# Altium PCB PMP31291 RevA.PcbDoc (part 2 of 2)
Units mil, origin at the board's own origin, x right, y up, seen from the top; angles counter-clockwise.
Board outline 2106.3 x 1624.03 mil, 4 copper layers (Top Layer, Layer 2, Layer 3, Bottom Layer), stack 73.2 mil thick; 65 components, 32 nets, 159 pads, 133 vias.
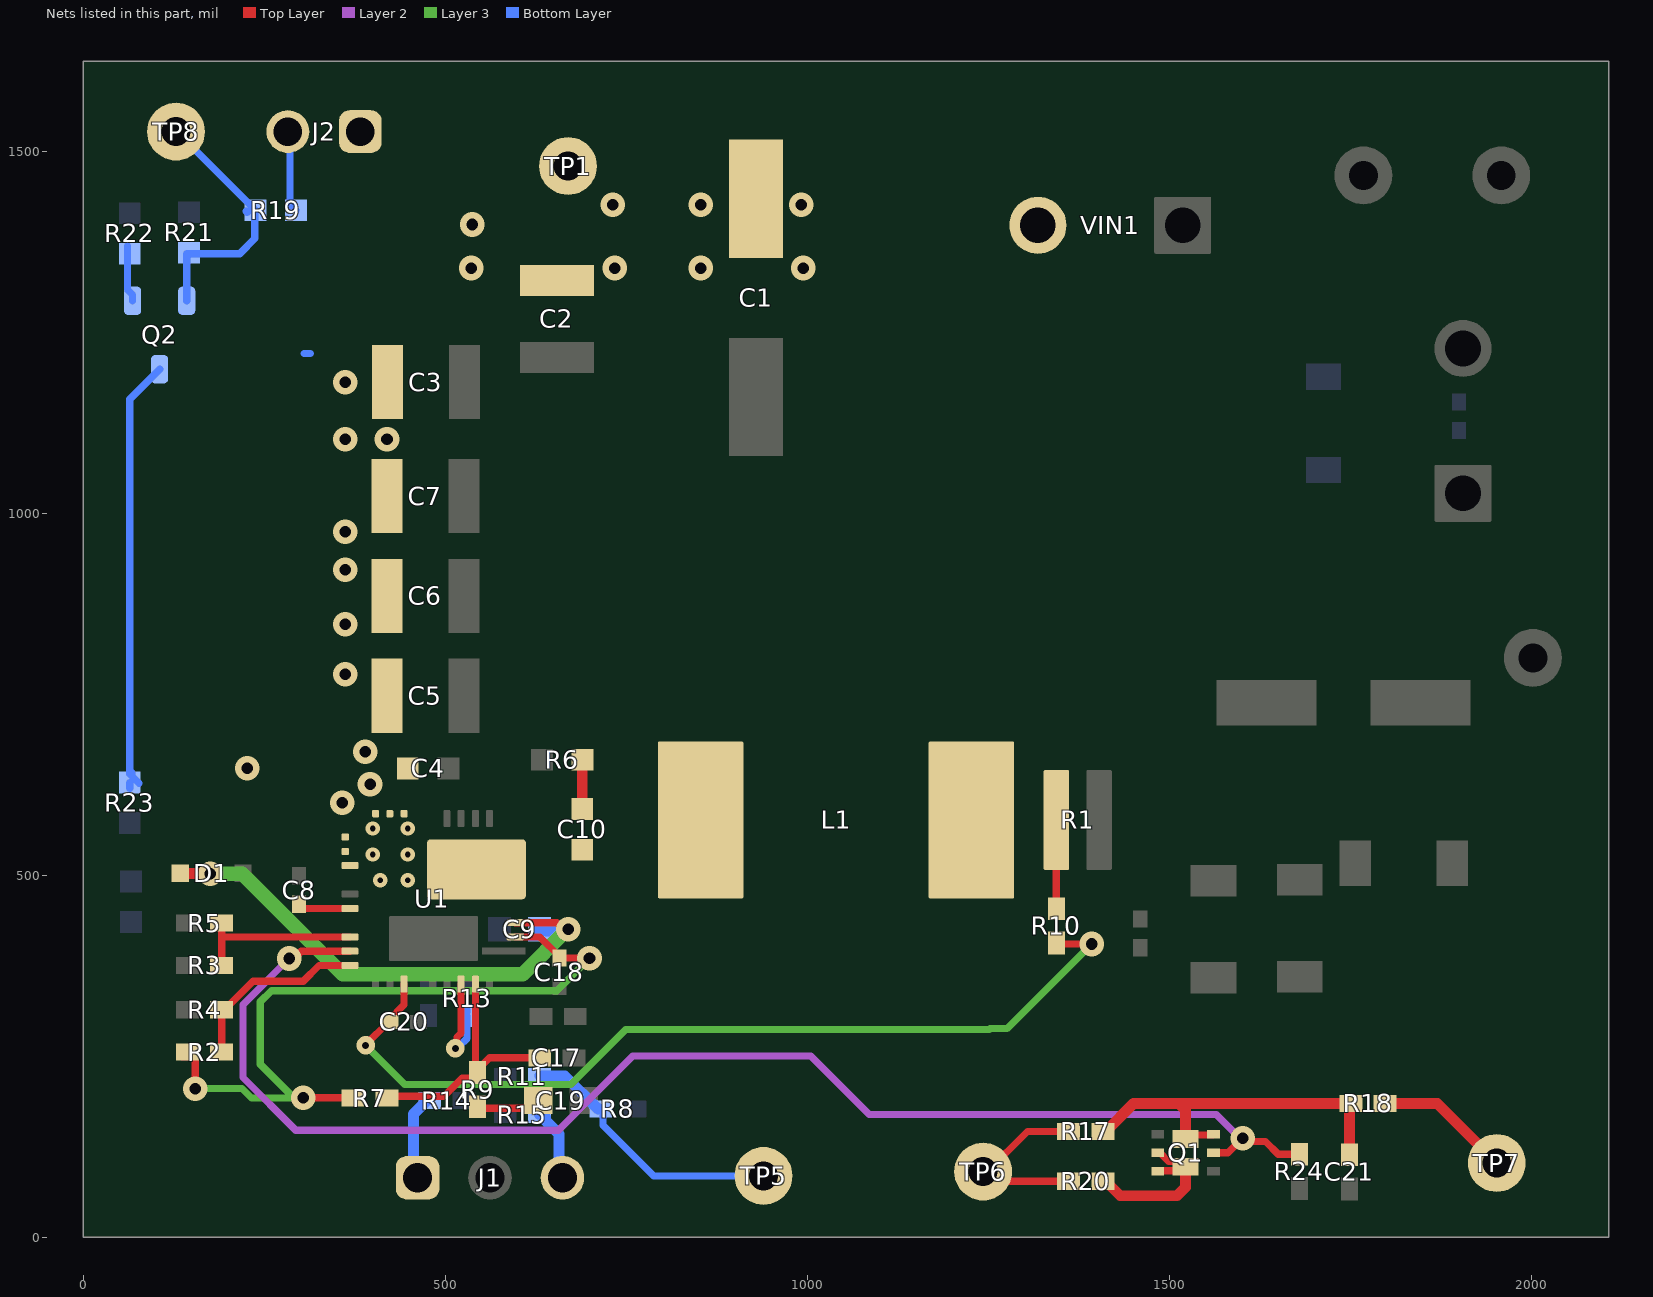
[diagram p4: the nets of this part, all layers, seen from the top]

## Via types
v1: diameter 34, hole 16, Top Layer to Bottom Layer, tented both sides, 117 vias
v2: diameter 19.68, hole 7.87, Top Layer to Bottom Layer, 12 vias
v3: diameter 25.75, hole 10, Top Layer to Bottom Layer, tented both sides, 4 vias

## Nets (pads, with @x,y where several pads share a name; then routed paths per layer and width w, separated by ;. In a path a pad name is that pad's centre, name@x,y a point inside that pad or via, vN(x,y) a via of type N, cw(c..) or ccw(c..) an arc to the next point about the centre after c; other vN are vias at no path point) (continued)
NetC10_2: C10.2 R6.1 | length 63.1
  Top Layer w10: R6.1@688.98,659.03 R6.1@689.39,659.45
  Top Layer w15: C10.2@688.98,596.51 R6.1@688.98,659.03
NetC17_1: C17.1 R7.1 R9.2 U1.15 | length 364.1
  Top Layer w10: R7.1@412.23,194.78 498.03,194.78 523.34,220.09 538.66,220.09 R9.2@544.29,225.72 ; U1.15@541.34,350 541.34,343.27 541.48,343.13 R9.2@541.48,227.56 ; R9.2@544.29,227.56 544.29,231.49 560.72,247.92 C17.1@630.28,247.92
NetC19_1: C19.1 R9.1 | length 81.3
  Top Layer w10: R9.1@544.29,178.47 C19.1@625.59,178.47
NetC20_2: C20.2 R10.2 U1.11 | length 1261.7
  Top Layer w10: v3(389.75,265.16) 389.75,266.01 421.26,297.52 C20.2@423.23,297.52 ; C20.2@421.22,299.53 442.91,321.22 U1.11@442.91,350 ; R10.2@1343.64,406.7 1345.17,405.16 v1(1392.46,405.16)
  Layer 3 w10: v3(389.75,265.16) 443.69,211.22 672.92,211.22 748.94,287.24 1251.05,287.24 1252.09,288.29 1275.59,288.29 v1(1392.46,405.16)
NetC21_1: C21.1 Q1.3 Q1.8 R17.1 R18.2 | length 523.8
  Top Layer w10: R17.1@1407.86,146.38 R17.1@1411.8,146.38 ; Q1.8@1522.04,136.06 1527.51,141.53 1559.52,141.53 Q1.3@1560.42,142.44 ; R18.2@1748.41,182.95 R18.2@1750.38,184.92
  Top Layer w15: R17.1@1411.8,146.38 1450.34,184.92 1513.02,184.92 ; Q1.8@1522.04,136.06 1522.04,175.9 1513.02,184.92 ; C21.1@1748.41,114.04 R18.2@1748.41,182.95 ; R18.2@1750.38,184.92 1513.02,184.92
NetJ1_1: J1.1 R14.1 | length 124.1
  Bottom Layer w10: R14.1@474.41,188.93 R14.1@478.35,188.93
  Bottom Layer w15: J1.1@455.71,76.52 455.71,170.23 R14.1@474.41,188.93
NetJ1_3: J1.3 R15.1 | length 105.6
  Bottom Layer w15: R15.1@629.87,169.7 633.81,169.7 638.12,165.39 638.12,161.46 656.65,142.92 J1.3@656.65,77.47
NetJ2_2: J2.2 R19.2 | length 123.7
  Bottom Layer w10: J2.2@282.45,1527.06 285.31,1524.2 285.31,1426.86 R19.2@293.75,1418.42 ; J2.2@289.76,1519.74 J2.2@297.08,1527.06
NetL1_2: L1.2 R1.1 R10.1 | length 122.5
  Top Layer w10: R10.1@1343.64,453.94 R1.1@1343.64,576.41
NetQ1_5: Q1.5 Q1.6 Q1.7 R20.1 | length 243.1
  Top Layer w10: R20.1@1407.86,77.48 R20.1@1411.8,77.48 ; Q1.6@1483.65,91.26 1484.56,92.16 1516.56,92.16 Q1.7@1522.04,97.64 1514.73,104.94 1498.51,104.94 1486.6,116.85 Q1.5@1483.65,116.85
  Top Layer w15: R20.1@1411.8,77.48 1431.78,57.5 1510.35,57.5 1522.04,69.19 1522.04,92.16 Q1.7@1522.04,97.64
NetQ2_1: Q2.1 R22.2 | length 79.2
  Bottom Layer w10: R22.2@60.78,1369.64 60.78,1308.91 67.94,1301.75 Q2.1@67.94,1293.39
NetQ2_2: Q2.2 R19.1 R21.2 TP8.1 | length 371.2
  Bottom Layer w10: TP8.1@127.95,1527.06 129.11,1527.06 R19.1@237.75,1418.42 236.77,1417.45 236.77,1379.24 215.97,1358.44 143.73,1358.44 R21.2@145.99,1356.18 ; Q2.2@142.74,1293.39 R21.2@142.74,1358.44 ; R19.1@224.7,1416.91 226.43,1415.17 R19.1@229.55,1418.29
NetQ2_3: Q2.3 R23.2 | length 609.2
  Bottom Layer w10: R23.2@63.98,619.73 R23.2@63.98,628.17 ; R23.2@65.73,642.87 66.96,641.64 R23.2@66.96,637.01 ; R23.2@76.96,627.01 R23.2@66.96,637.01 ; Q2.3@105.34,1198.9 63.98,1157.53 63.98,639.99 R23.2@66.96,637.01
NetR2_1: R2.1 R4.2 U1.8 | length 261
  Top Layer w10: R2.1@190.94,255.91 R4.2@190.94,314.34 194.88,314.34 234.25,353.71 303.49,353.71 325.37,375.59 U1.8@368.11,375.59
NetR3_1: R3.1 R5.2 U1.6 | length 234
  Top Layer w10: R3.1@190.94,375.59 190.94,413.39 R5.2@190.94,434.02 ; 192.52,414.96 258.75,414.96 U1.6@368.11,414.96
NetR8_1: R8.1 R11.2 TP5.1 | length 377.5
  Bottom Layer w10: R11.2@629.87,222.35 R11.2@630.83,223.31 ; R8.1@717.42,177.49 717.42,154.74 787.22,84.95 TP5.1@939.23,84.95
  Bottom Layer w15: R11.2@630.83,223.31 664.81,223.31 710.63,177.49 R8.1@714.57,177.49
NetR17_2: R17.2 R20.2 TP6.1 | length 272.7
  Top Layer w10: TP6.1@1234.93,77.48 R20.2@1360.62,77.48 ; TP6.1@1236.6,90.84 1248.29,90.84 1303.83,146.38 R17.2@1360.62,146.38
NetR18_1: R18.1 TP7.1 | length 188.2
  Top Layer w15: R18.1@1797.63,184.92 1869.6,184.92 TP7.1@1951.79,102.72
PG: Q1.2 R24.2 U1.7 | length 1924.3
  Top Layer w10: v1(284.1,385.09) 290.59,385.09 300.78,395.28 U1.7@368.11,395.28 ; Q1.2@1560.42,116.85 1580.63,116.85 v1(1600.78,137) 1605.37,132.4 1632.47,132.4 1649.99,114.88 R24.2@1679.36,114.88 R24.2@1679.36,118.82
  Layer 2 w10: v1(284.1,385.09) 220.37,321.36 220.37,220.84 293.11,148.1 656.27,148.1 758.68,250.51 1004.47,250.51 1085.27,169.7 1564.38,169.7 1597.09,137 v1(1600.78,137)
  Bottom Layer w10: v1@280.54,381.53 v1(284.1,385.09)
RT: R13.2 U1.14 | length 145.2
  Top Layer w10: v3@514.03,261.91 515.88,263.77 515.88,276.58 521.65,282.34 U1.14@521.65,350
  Bottom Layer w10: v3@518.7,260.96 518.7,263.59 529.94,274.83 R13.2@529.94,306.32 ; R13.2@529.94,310.78 R13.2@529.94,314.72
  other v3: 513.76,260.96
SW: C10.1 L1.1 U1. U1.20 U1.21 U1.22 | length 0.1
  Top Layer w10: U1.22@602.52,533.07 U1.@602.6,532.99
SW1: C8.2 U1.5 | length 73.9
  Top Layer w10: C8.2@297.83,460.79 297.83,459.17 302.67,454.33 U1.5@368.11,454.33
VCC: C9.1 D1.2 U1.19 | length 738.3
  Top Layer w10: D1.2@132.99,502.01 D1.2@133.86,502.87 ; U1.19@596.46,434.65 653.9,434.65 662.96,425.59 v1(669.45,425.59)
  Top Layer w15: D1.2@132.99,502.01 134.61,503.62 135.79,502.44 174.82,502.44 v1(175.26,502.01)
  Layer 3 w20: v1(175.26,502.01) 219.58,502.01 296.22,425.36 357.96,363.62 606.51,363.62 668.48,425.59 v1(669.45,425.59)
  Bottom Layer w20: C9.1@629.87,425.59 v1(669.45,425.59)
VDDA: C18.2 R2.2 R7.2 U1.18 | length 1033.9
  Top Layer w10: R2.2@136.89,249.09 R2.2@143.7,249.09 ; R2.2@143.7,255.91 147.64,255.91 154.45,249.09 v1(154.45,205.5) ; v1(303.49,192.98) 303.74,192.73 371.64,192.73 R7.2@371.89,192.48 ; U1.18@596.46,414.96 630.31,414.96 657.51,387.77 C18.2@657.51,385.8 657.59,385.72 698.9,385.72 v1(698.98,385.63)
  Layer 3 w10: v1(154.45,205.5) 219.2,205.5 232.22,192.48 v1@290.48,192.48 ; v1(303.49,192.98) 290.48,192.98 244.37,239.08 244.37,325.45 259.67,340.75 654.09,340.75 v1(698.98,385.63)
VIN: C1.1 C2.1 C3.1 C4.1 C5.1 C6.1 C7.1 J2.1 TP1.1 U1.1 U1.2 U1.3 U1.27 U1.28 U1.29 VIN1.2 | length 8.5
  Bottom Layer w10: 305.07,1220.47 313.54,1220.47
  other v1: 357.56,600.17 395.9,625.81 226.23,647.64 389.06,670.87 361.57,777.56 361.57,846.46 361.57,921.82 361.57,974.41 361.57,1102.36 419.29,1102.36 361.57,1181.1 535.43,1338.58 733.64,1338.58 852.36,1338.58 994.09,1338.58 537.06,1398.78 730.95,1425.76 852.36,1425.76 991.41,1425.76
  other v2: 410.08,493.07 447.83,493.07 399.61,528.82 447.83,528.82 399.61,564.57 447.83,564.57
pads on no net: U1.10

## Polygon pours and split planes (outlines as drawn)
AGND on Top Layer "AGND_L01_P036" (solid, remove dead copper, pour order 36): 585.47,401.15 585.47,381.98 661.39,306.05 661.39,147.64 711.61,147.64 708.45,150.8 708.45,321.93 630.46,399.92
SW on Top Layer "SW_L01_P039" (solid, remove dead copper, pour order 39): 912.58,467.21 ccw(c903.08,477.47) 917.05,476.94 917.05,675.88 ccw(c901.81,675.89) 912.58,686.67 ccw(c906.1,680.2) 906.09,689.36 799.51,689.36 ccw(c799.5,673.33) 788.17,684.66 788.12,684.62 ccw(c801.85,670.88) 782.43,670.87 782.43,590.17 cw(c732.21,590.17) 767.72,554.66 cw(c759.32,563.05) 757.22,551.37 504.16,549.13 ccw(c504.79,477.29) 478.07,543.98 478.07,495.28 ccw(c504.56,485.64) 483.47,466.94
VIN on Top Layer "VIN_L01_P004" (solid, remove dead copper, pour order 4): 462.45,1624.01 462.77,478.87 394.39,478.65 370.16,502.87 0,502.87 0,1624.01
VIN on Top Layer "VIN_L01_P002" (solid, remove dead copper, pour order 2): 559.13,1275.49 1433.3,1275.49 1433.3,1617.27 1430.11,1620.47 314.22,1620.47 314.22,1275.49
GND on Top Layer "GND_L01_P050" (solid, remove dead copper, pour order 50): -56.42,1646.33 2049.88,1646.33 2049.88,22.32 -56.42,22.32
-VOUT on Top Layer "-VOUT_L01_P049" (solid, remove dead copper, pour order 49): 490.68,1102.36 610.24,1102.36 757.87,954.72 757.87,905.51 490.68,905.51
-VOUT on Top Layer "-VOUT_L01_P027" (solid, remove dead copper, pour order 27): 912.58,716.39 906.32,353.71 1058.84,222.68 1511.1,222.68 1518.49,222.68 2086.61,222.68 2086.61,379.91 2086.61,407.24 1199.07,407.24 1151.03,714.21
-VOUT on Top Layer "-VOUT_L01_P030" (solid, remove dead copper, pour order 30): 2106.3,1132.24 2106.3,222.68 1808.5,222.68 1808.5,1127.55 1813.19,1132.24
GND on Top Layer "GND_L01_P048" (solid, remove dead copper, pour order 48): 1389.65,644.89 1389.83,645.07 1419.75,645.07 1459.57,684.88 1459.57,466.39 1418.14,507.82 1390.82,507.82
NetL1_2 on Top Layer "NETL1_2_L01_P046" (solid, remove dead copper, pour order 46): 1287.08,684.66 1331.98,639.76 1358.93,639.76 1358.93,537.38 1290.07,468.52 1170.16,468.52 1170.16,684.66
-VOUT on Top Layer "-VOUT_L01_P043" (solid, remove dead copper, pour order 43): 386.4,460.79 388.02,459.17 580.71,459.17 580.71,364.83 385.42,364.83
VIN on Top Layer "VIN_L01_P041" (solid, pour order 41): 326.8,530.89 358.27,530.89 358.27,499.29 357.6,498.62
-VOUT on Top Layer "-VOUT_L01_P040" (solid, remove dead copper, pour order 40): 462.6,561.34 463.4,560.53 650,560.53 650,691.09 650.89,690.2 1152,690.2 1152,954.72 462.6,954.72
VIN on Bottom Layer "VIN_L04_P019" (solid, remove dead copper, pour order 19): 440.62,1115.93 607.94,1283.26 1423.54,1283.26 1423.54,1624.55 1420.34,1627.74 -7.43,1627.74 -7.43,1115.93
GND on Bottom Layer "GND_L04_P051" (solid, remove dead copper, pour order 51): 0,1122.05 0,1624.02 2106.3,1624.02 2106.3,1123.99
-VOUT on Bottom Layer "-VOUT_L04_P045" (solid, remove dead copper, pour order 45): 2106.3,1123.99 2106.3,1.94 0,1.94 0,385.37 0,1123.99
VIN on Bottom Layer "VIN_L04_P042" (solid, remove dead copper, pour order 42): 0,1212.68 462.6,1212.68 462.6,472.44 0,472.44
-VOUT on Layer 2 "-VOUT_L02_P014" (solid, remove dead copper, pour order 14): 2083.91,1607.38 2083.91,-16.64 -22.39,-16.64 -22.39,1607.38
VIN on Layer 3 "VIN_L03_P013" (solid, remove dead copper, pour order 13): 448.06,1112.2 615.38,1279.53 1430.97,1279.53 1430.97,1620.82 1427.78,1624.02 0,1624.02 0,1112.2
VIN on Layer 3 "VIN_L03_P016" (solid, remove dead copper, pour order 16): 559.13,1275.49 1433.3,1275.49 1433.3,1617.27 1430.11,1620.47 314.22,1620.47 314.22,1275.49
VIN on Layer 3 "VIN_L03_P007" (solid, remove dead copper, pour order 7): 462.45,1624.01 462.77,478.87 394.39,478.65 370.16,502.87 0,502.87 0,1624.01
GND on Layer 3 "GND_L03_P034" (solid, remove dead copper, pour order 34): 2106.3,1624.02 2106.3,0 0,0 0,383.86 0,1624.02

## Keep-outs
Keep-Out Layer:
  text ".Layer_Name" at -165.69,-817.99 h60

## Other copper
Top Layer:
  pour cut-out: 650,691.09 650,560.53 728.35,560.53 728.35,691.62
  pour cut-out: 1358.93,500.85 1358.93,378.16 1440.49,378.16 1440.49,500.85
  pour cut-out: 162.9,237.13 162.9,370.43 172.86,380.39 177.66,375.59 473.09,375.59 473.09,241.47 465.06,233.44
  pour cut-out: 925.2,482.28 928.8,482.28 929.03,482.52
  pour cut-out: 938.22,462.36 939.23,461.35 939.23,321.93 938.1,321.93 928.8,343.13 928.8,376.19 928.8,458.54
  pour cut-out: 789.64,205.5 789.64,146.31 846.46,146.31 846.46,205.5
  pour cut-out: 561.02,442.91 561.02,358.34 585.47,358.34 585.47,446.64 585.3,446.81
  pour cut-out: 106.06,542.24 141.9,392.32 297.83,392.32 353.16,493.04 323.72,540.64
  pour cut-out: 1152,464.24 1152.46,463.78 1152.46,436.76 1212.48,436.76 1213.54,435.7 1213.54,463.45
  pour cut-out: 1152.46,436.76 1213.54,375.68 1371.89,375.68 1371.89,434.65
  text ".Layer_Name" at -244.43,-817.99 h60
Layer 3:
  pour cut-out: 1361.05,483.54 1361.05,424.34 1417.87,424.34 1417.87,483.54
  pour cut-out: 789.29,203.74 789.29,144.54 846.11,144.54 846.11,203.74
  pour cut-out: 387.11,463.14 390.93,459.33 390.93,385.09 597,385.09 598.07,384.01 599.45,385.4 599.45,460.68
  pour cut-out: 402.17,288.29 402.17,229.09 458.99,229.09 458.99,288.29
  pour cut-out: 1610.04,656.8 1610.04,597.61 1666.86,597.61 1666.86,656.8
Bottom Layer:
  pour cut-out: 0,1094.47 127.95,1094.47 127.95,1165.92 275.04,1313.01 275.04,1341.73 334.65,1401.33 334.65,1616.13 0,1616.13
  pour cut-out: 29.53,442.91 47.48,460.87 47.48,472.44 205.92,472.44 233.18,445.17
  text ".Layer_Name" at -165.69,-817.99 h60

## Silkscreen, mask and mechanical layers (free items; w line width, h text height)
Top Overlay:
  text "'.PRJ_Number'.PCB_Rev" at 145.46,620.08 h108.27 r90
  text ".Layer_Name" at -165.69,-817.99 h60
Bottom Overlay:
  text ".Layer_Name" at -165.69,-817.99 h60
Top Paste:
  text ".Layer_Name" at -165.69,-817.99 h60
Bottom Paste:
  text ".Layer_Name" at -165.69,-817.99 h60
Top Solder:
  text ".Layer_Name" at -165.69,-817.99 h60
  text ".Layer_Name" at -165.69,-817.99 h60
Bottom Solder:
  text ".Layer_Name" at -165.69,-817.99 h60
Drill Guide:
  text ".Layer_Name" at -165.69,-817.99 h60
M1 Board Outline:
  the board outline again, w10
  text ".Layer_Name" at -244.43,-817.99 h60
M2 Board Dimensions:
  rectangle: -617.69,-359.49 -242.69,-234.49
  rectangle: -742.69,-234.49 -617.69,-109.49
  lines w7: -742.69,-234.49 257.31,-234.49 ; -617.69,-359.49 -617.69,-109.49 ; -492.69,-359.49 -492.69,-109.49 ; -242.69,-359.49 -242.69,-109.49 ; 7.31,-359.49 7.31,-109.49 ; -742.69,-359.49 -742.69,-109.49 257.31,-109.49 257.31,-359.49 -742.69,-359.49
  text ".Layer_Name" at -244.43,-817.99 h60
Mechanical 3:
  text ".Layer_Name" at -244.43,-817.99 h60
Mechanical 4:
  text ".Layer_Name" at -244.43,-817.99 h60
Mechanical 5:
  lines w10: -1054.37,-889.66 4795.66,-889.66 ; -1054.37,-686.33 4795.66,-686.33 ; -1054.37,-482.99 -1054.37,-1092.99 2950.63,-1092.99 ; 521.63,-1092.99 -1053.87,-1092.99 -1053.87,-482.99 4795.66,-482.99 4795.66,-1092.99 2474.25,-1092.99 ; 1229.52,-1092.99 1229.52,-482.99 ; 2260.3,-686.33 2260.3,-482.99 ; 2982.19,-686.33 2982.19,-482.99 ; 3486.08,-1099.49 3486.08,-896.66
  text "COMPONENTS MARKED 'DNP' SHOULD NOT BE POPULATED." at 288.76,-277.99 h60
  text "ASSEMBLY VARIANT:" at 288.26,-393.49 h60
  text ".VariantName" at 1316.39,-393.49 h60
  text "PCB VIEWED FROM TOP SIDE" at -1010.56,-615.16 h60
  text "BOARD #:" at 1273.03,-615.16 h60
  text ".PRJ_Number" at 1731.91,-615.16 h60
  text "REV:" at 2418.93,-615.16 h60
  text ".PCB_Rev" at 2651.38,-615.16 h60
  text "SVN REV:" at 3052.21,-615.16 h60
  text ".VersionControl_RevNumber" at 3546.4,-615.16 h60
  text "TID #:" at 1273.03,-818.49 h60
  text ".TID" at 1731.91,-818.49 h60
  text "PLOT NAME =" at -1010.56,-1023.83 h60
  text ".plot_File_Name" at -244.43,-1023.83 h60
  text "GENERATED    :" at 1275.03,-1023.83 h60
  text ".Print_Date" at 1998.86,-1023.83 h60
  text ".Print_Time" at 2590.06,-1023.83 h60
  text "TEXAS INSTRUMENTS" at 3657.71,-1023.83 h60
Mechanical 6:
  lines w10: -1054.87,-686.83 4795.66,-686.83 ; -1052.87,-890.16 4795.66,-890.16 ; 270.45,-1099.99 270.45,-897.16 ; 813.71,-686.83 813.71,-483.49 ; 1301.97,-1093.49 4795.66,-1093.49 3337.27,-1093.49 ; 1542.13,-1093.49 -1054.87,-1093.49 -1054.87,-483.49 4795.66,-483.49 ; 1555.28,-686.83 1555.28,-483.49 ; 2586.06,-1093.49 2586.06,-483.49 ; 4794.66,-1093.49 4794.66,-483.49 ; 4795.16,-1093.49 4795.16,-483.49
  text "COMPONENTS MARKED 'DNP' SHOULD NOT BE POPULATED." at 4961.67,-277.49 h60
  text ".VariantName" at 3622.4,-393.49 h60
  text "ASSEMBLY VARIANT:" at 4622.03,-393.49 h60
  text ".VersionControl_RevNumber" at 292.81,-615.66 h60
  text "SVN REV:" at 779.13,-615.66 h60
  text ".PCB_Rev" at 1183.89,-615.66 h60
  text "REV:" at 1424.21,-615.66 h60
  text ".PRJ_Number" at 2024.62,-615.66 h60
  text "BOARD #:" at 2491.38,-615.66 h60
  text "PCB VIEWED FROM BOTTOM SIDE" at 4751.34,-615.66 h60
  text ".TID" at 2044.3,-818.99 h60
  text "TID #:" at 2491.38,-818.99 h60
  text "TEXAS INSTRUMENTS" at 102.76,-1024.33 h60
  text ".Print_Time" at 1284.58,-1024.33 h60
  text ".Print_Date" at 1903.34,-1024.33 h60
  text "GENERATED    :" at 2686.23,-1024.33 h60
  text ".plot_File_Name" at 4083.64,-1024.33 h60
  text "PLOT NAME =" at 4751.34,-1024.33 h60
M9 Title Sheet:
  drawing of 55 lines, arcs and shapes, not listed
  text "1" at -81.85,5372.01 h70
  text "2" at 2276.16,5372.01 h70
  text "3" at 4652.81,5372.01 h70
  text "4" at 7028.16,5372.01 h70
  text "A" at -1179.19,4482.01 h70
  text "A" at 8115.81,4482.01 h70
  text "B" at -1179.19,2606.01 h70
  text "B" at 8115.81,2606.01 h70
  text "C" at -1179.19,730.01 h70
  text "C" at 8115.81,730.01 h70
  text "PROJECT TITLE:" at 5080.81,-381.99 h45
  text ".PRJ_Title" at 5130.81,-515.32 h70
  text "DESIGNED FOR:" at 5080.81,-682.99 h45
  text ".PRJ_Customer" at 5130.81,-822.99 h70
  text "FILE NAME:" at 5080.81,-982.99 h45
  text ".PCB_File_Name_No_Path" at 5130.81,-1102.99 h70
  text "D" at -1179.19,-1141.99 h70
  text "D" at 8115.81,-1141.99 h70
  text "Texas Instruments (TI) and/or its licensors do not warrant the accuracy or completeness of this specification" at 221.31,-1264.83 h45
  text "ENGINEER:" at 5080.81,-1272.99 h45
  text "LAYOUT BY:" at 6585.81,-1272.99 h45
  text "or any information contained therein. TI and/or its licensors do not warrant that this design will meet" at 176.33,-1377.5 h45
  text ".PRJ_Engineer" at 5130.81,-1427.98 h70
  text ".PCB_Layout" at 6636.31,-1427.98 h70
  text "the specifications, will be suitable for your application or fit for any particular purpose, or will operate in" at 176.33,-1490.16 h45
  text "ALTIUM DESIGNER VERSION:" at 6585.81,-1582.99 h45
  text "an implementation. TI and/or its licensors do not warrant that the design is production worthy. You should" at 176.33,-1602.83 h45
  text "completely validate and test your design implementation to confirm the system functionality for your application." at 221.31,-1715.49 h40
  text ".print_Scale" at 5130.81,-1716.32 h70
  text ".Application_BuildNumber" at 6636.31,-1716.32 h70
  text "1" at -81.85,-1927.99 h70
  text "2" at 2276.16,-1927.99 h70
  text "3" at 4652.81,-1927.99 h70
  text "4" at 7028.16,-1927.99 h70
M10 Fab Notes:
  drawing of 189 lines, arcs and shapes, not listed
  text "DESIGN INFORMATION" at 6116.83,5202.18 h60
  text "MIN. TRACK WIDTH:" at 5472.27,5070.06 h60
  text "10" at 6568.51,5070.06 h60
  text "MIL" at 6723.27,5070.06 h60
  text "7.874" at 6397.64,4950.79 h60
  text "MIN. CLEARANCE:" at 5472.27,4945.93 h60
  text "MIL" at 6723.27,4945.93 h60
  text "MIN. VIA PAD SIZE:" at 5472.27,4821.8 h60
  text "24" at 6538.52,4821.81 h60
  text "MIL" at 6723.27,4821.8 h60
  text "0.05mm (2MIL)" at 6167.27,4691.9 h60
  text "MINIMUM ANNULAR RING" at 5143.04,4683.68 h60
  text "EXTERNAL" at 6875.27,4683.68 h60
  text "PER" at 5343.04,4573.56 h60
  text "IPC-D-275 CLASS 2 LEVEL C" at 5563.04,4573.55 h60
  text "MIL, HOLES" at 7051.27,4473.08 h60
  text "+/-" at 6658.81,4464.49 h60
  text "+/-" at 7512.81,4464.49 h60
  text "REGISTRATION TOLERANCES:" at 5143.04,4463.43 h60
  text "METAL" at 6342.81,4463.43 h60
  text "5" at 6919.01,4463.43 h60
  text "3" at 7752.01,4463.43 h60
  text "MIL" at 7868.27,4463.43 h60
  text "HOLE SIZE TOLERANCE (UNLESS OTHERWISE SPECIFIED):" at 5143.04,4365.11 h60
  text "+/-" at 7512.81,4362.24 h60
  text "3" at 7752.01,4361.18 h60
  text "MIL" at 7868.27,4361.17 h60
  text "MATERIAL:" at 5068.27,4223.53 h60
  text "FR-4 High Tg" at 6054.71,4095 h60
  text "X" at 5910.28,4087.01 h60
  text "FR-4" at 5489.27,4082.5 h60
  text "OTHER" at 6977.27,4082.5 h60
  text "62 MIL (1.6mm) +/-10%" at 5809.37,3939.47 h60
  text "X" at 5689.28,3937.01 h60
  text "THICKNESS:" at 5143.04,3931.25 h60
  text "OTHER" at 7094.27,3931.25 h60
  text "TOLERANCE:" at 5143.04,3792.93 h60
  text "X" at 5991.28,3792.93 h60
  text "ANSI IPC-6012 TYPE 3 CLASS 2" at 6169.29,3792.93 h60
  text "OTHER +/-" at 6169.27,3648.74 h60
  text "BOW & TWIST:" at 5143.04,3503.55 h60
  text "X" at 5991.28,3503.55 h60
  text "ANSI IPC-6012 TYPE 3 CLASS 2" at 6169.29,3503.55 h60
  text "OTHER +/-" at 6169.27,3356.86 h60
  text "DRILLING:" at 5068.27,3226.24 h60
  text "NC_DRILL FILES" at 6829.27,3121.05 h60
  text "REFERENCE:" at 5143.04,3117.11 h60
  text "X" at 5800.28,3117.01 h60
  text "AS SHOWN" at 5978.27,3117.11 h60
  text "X" at 6701.28,3117.11 h60
  text "OTHER" at 7127.27,2974.86 h60
  text "PTH COPPER THICKNESS:" at 5142.72,2971.33 h60
  text "X" at 6281.95,2971.33 h60
  text "20-30 um" at 6409.95,2971.33 h60
  text "BOARD FINISH:" at 5068.27,2823.73 h60
  text "SILKSCREEN:" at 5223.49,2713.61 h60
  text "X" at 6181.28,2713.61 h60
  text "TOP" at 6298.27,2713.61 h60
  text "X" at 6691.28,2713.61 h60
  text "BOTTOM" at 6809.27,2713.61 h60
  text "SILKSCREEN COLOR:" at 5223.49,2558.42 h60
  text "X" at 6180.28,2558.42 h60
  text "WHITE" at 6298.27,2558.42 h60
  text "OTHER" at 6809.27,2558.42 h60
  text "X" at 6311.28,2414.97 h60
  text "GREEN" at 6429.27,2414.97 h60
  text "OTHER" at 7047.27,2414.97 h60
  text "SOLDER RESIST COLOR:" at 5223.49,2408.1 h60
  text "X" at 6311.28,2260.72 h60
  text "MATTE" at 6429.27,2260.72 h60
  text "SEMI-GLOSS" at 7046.81,2260.08 h60
  text "IMMERSION GOLD (ENIG)" at 6129.27,2087.95 h60
  text "ENEPIG" at 7466.81,2080.73 h60
  text "SURFACE FINISH:" at 5068.27,2079.73 h60
  text "X" at 6653.54,1948.82 h60
  text "IMM. TIN/SILVER OR EQUIV" at 5397.81,1942.41 h60
  text "OTHER" at 6829.27,1938.47 h60
  text "ARRAY/PANEL:" at 5068.27,1783.1 h60
  text "CUT AND TRIM PER M1 BOARD OUTLINE" at 6129.27,1774.87 h60
  text "N.C. ROUTE" at 6129.27,1638.91 h60
  text "X" at 6817.28,1638.91 h60
  text "V. SCORE" at 6995.27,1638.91 h60
  text "CERTIFICATION:" at 5068.27,1509.78 h60
  text "MATERIALS AND WORKMANSHIP FOR ALL PCBS" at 5793.27,1509.78 h60
  text "TO MEET OR EXCEED THE REQUIREMENTS OF:" at 5793.27,1415.72 h60
  text "X" at 5430.78,1287.09 h60
  text "ANSI IPC-A-600F CLASS ->" at 5558.77,1287.09 h60
  text "X" at 7206.78,1287.09 h60
  text "2" at 7316.77,1287.09 h60
  text "1" at 7001.77,1285.59 h60
  text "3" at 7670.77,1285.59 h60
  text "X" at 6242.78,1139.4 h60
  text "RoHS" at 6370.77,1139.4 h60
  text "OTHER" at 7015.18,1139.4 h60
  text "PER ORDER" at 7412.23,1139.4 h60
  text "ALL BOARDS MUST MEET OR EXCEED UL94-V0 REQUIREMENTS." at 5095.81,985.57 h60
  text "PCB MUST BEAR THE UL94V-0 UL REGISTERED MATERIAL ID NUMBER" at 5095.81,869.51 h60
  text "ADDITIONAL REQUIREMENTS:" at 5068.27,700.09 h60
  text "MICROSECTION:" at 5143.04,592.96 h60
  text "YES" at 6048.77,592.96 h60
  text "X" at 6328.74,452.76 h60
  text "REQUIRED" at 6910.27,448.63 h60
  text "BARE BOARD ELEC. TEST:" at 5143.04,445.77 h60
  text "NONE" at 6448.77,445.77 h60
  text "PER ORDER" at 7502.27,445.77 h60
  text "XX MIL VIAS REQUIRE NON-CONDUCTIVE FILL AND PLANARIZE" at 5311.19,240.83 h59
  text "XX MIL VIAS REQUIRE CONDUCTIVE FILL AND PLANARIZE" at 5319.19,136.85 h60
  text "OUTER XX MIL TRACES REQUIRE 50 OHM SINGLE-ENDED IMPEDANCE" at 5318.2,-26.54 h58
  text "LAYER 2 & 3 (INNER LAYERS) XX MIL WIDE, XX MIL SPACE / TRACES REQUIRE 100 OHM DIFFERENTIAL IMPEDANCE" at 5310.2,-262.25 h60
  text ".Layer_Name" at -244.43,-817.99 h60
M11 Gerber Information:
  lines w10: -1054.37,-889.66 4795.66,-889.66 ; -1054.37,-686.33 4795.66,-686.33 ; -1054.37,-482.99 -1054.37,-1092.99 2950.63,-1092.99 ; 521.63,-1092.99 -1053.87,-1092.99 -1053.87,-482.99 4795.66,-482.99 4795.66,-1092.99 2474.25,-1092.99 ; 1229.52,-1092.99 1229.52,-482.99 ; 2260.3,-686.33 2260.3,-482.99 ; 2982.19,-686.33 2982.19,-482.99 ; 3486.08,-1099.49 3486.08,-896.66
  text "ALL ARTWORK VIEWED FROM TOP SIDE" at -1010.56,-615.16 h60
  text "BOARD #:" at 1273.03,-615.16 h60
  text ".PRJ_Number" at 1731.91,-615.16 h60
  text "REV:" at 2418.93,-615.16 h60
  text ".PCB_Rev" at 2651.38,-615.16 h60
  text "SVN REV:" at 3052.21,-615.16 h60
  text ".VersionControl_RevNumber" at 3546.4,-615.16 h60
  text "LAYER NAME =" at -1010.56,-817.99 h60
  text "TID #:" at 1273.03,-818.49 h60
  text ".TID" at 1731.91,-818.49 h60
  text "PLOT NAME =" at -1010.56,-1023.83 h60
  text ".plot_File_Name" at -244.43,-1023.83 h60
  text "GENERATED    :" at 1275.03,-1023.83 h60
  text ".Print_Date" at 1998.86,-1023.83 h60
  text ".Print_Time" at 2590.06,-1023.83 h60
  text "TEXAS INSTRUMENTS" at 3657.71,-1023.83 h60
M12 Stackup:
  drawing of 295 lines, arcs and shapes, not listed
  text "Layer" at 355.31,5030.01 h60
  text "Name" at 765.22,5030.01 h60
  text "Material" at 1694.97,5030.01 h60
  text "Thickness" at 2554.74,5030.01 h60
  text "Constant" at 3204.57,5030.01 h60
  text "Board Layer Stack" at 3774.43,5030.01 h60
  text "Top Overlay" at 765.22,4910.01 h60
  text "Top Solder" at 765.22,4790.01 h60
  text "Solder Resist" at 1694.97,4790.01 h60
  text "0.40mil" at 2554.74,4790.01 h60
  text "3.5" at 3204.57,4790.01 h60
  text "1" at 355.31,4670.01 h60
  text "Top Layer" at 765.22,4670.01 h60
  text "2.80mil" at 2554.74,4670.01 h60
  text "Dielectric 1" at 765.22,4550.01 h60
  text "PP-006" at 1694.97,4550.01 h60
  text "2.80mil" at 2554.74,4550.01 h60
  text "4.1" at 3204.57,4550.01 h60
  text "2" at 355.31,4430.01 h60
  text "Layer 2" at 765.22,4430.01 h60
  text "CF-004" at 1694.97,4430.01 h60
  text "1.40mil" at 2554.74,4430.01 h60
  text "Dielectric1" at 765.22,4310.01 h60
  text "FR-4 High Tg" at 1694.97,4310.01 h60
  text "59.20mil" at 2554.74,4310.01 h60
  text "4.8" at 3204.57,4310.01 h60
  text "3" at 355.31,4190.01 h60
  text "Layer 3" at 765.22,4190.01 h60
  text "CF-004" at 1694.97,4190.01 h60
  text "1.40mil" at 2554.74,4190.01 h60
  text "Dielectric 2" at 765.22,4070.01 h60
  text "PP-006" at 1694.97,4070.01 h60
  text "2.80mil" at 2554.74,4070.01 h60
  text "4.1" at 3204.57,4070.01 h60
  text "4" at 355.31,3950.01 h60
  text "Bottom Layer" at 765.22,3950.01 h60
  text "2.80mil" at 2554.74,3950.01 h60
  text "Bottom Solder" at 765.22,3830.01 h60
  text "Solder Resist" at 1694.97,3830.01 h60
  text "0.40mil" at 2554.74,3830.01 h60
  text "3.5" at 3204.57,3830.01 h60
  text "Bottom Overlay" at 765.22,3710.01 h60
  text ".Layer_Name" at -244.43,-817.99 h60
Mechanical 13:
  text ".Layer_Name" at -244.43,-817.99 h60
Mechanical 14:
  text ".Layer_Name" at -244.43,-817.99 h60
Mechanical 15:
  text ".Layer_Name" at -244.43,-817.99 h60
Mechanical 16:
  text ".Layer_Name" at -244.43,-817.99 h60
Drill Drawing:
  lines w10: 1765.97,3043.69 1821.3,3043.69 1793.64,2988.36 1765.97,3043.69 ; 1765.97,3112.86 1765.97,3126.69 1779.8,3140.52 1765.97,3154.36 1765.97,3168.19 1779.8,3168.19 1793.64,3154.36 1807.47,3168.19 1821.3,3168.19 1821.3,3154.36 1807.47,3140.52 1821.3,3126.69 1821.3,3112.86 1807.47,3112.86 1793.64,3126.69 1779.8,3112.86 1765.97,3112.86 ; 1765.97,3251.19 1779.8,3251.19 1793.64,3237.36 1807.47,3251.19 1821.3,3251.19 1807.47,3265.02 1821.3,3278.86 1807.47,3278.86 1793.64,3292.69 1779.8,3278.86 1765.97,3278.86 1779.8,3265.02 1765.97,3251.19 ; 1765.97,3375.69 1779.8,3375.69 1779.8,3361.86 1807.47,3361.86 1807.47,3375.69 1821.3,3375.69 1821.3,3403.36 1807.47,3403.36 1807.47,3417.19 1779.8,3417.19 1779.8,3403.36 1765.97,3403.36 1765.97,3375.69 ; 1765.97,3486.36 1821.3,3486.36 1821.3,3541.69 1765.97,3541.69 1765.97,3486.36 ; 1765.97,3638.52 1793.64,3610.86 1821.3,3638.52 1793.64,3666.19 1765.97,3638.52 ; 1765.97,3735.36 1793.64,3749.19 1821.3,3735.36 1807.47,3763.02 1821.3,3790.69 1793.64,3776.86 1765.97,3790.69 1779.8,3763.02 1765.97,3735.36
  lines w12: 1715.81,2951.01 4948,2951.01 ; 1715.81,3822.51 4948,3822.51 ; 2053.82,2826.51 2053.82,3947.01 ; 2385.98,2826.51 2385.98,3947.01 ; 3022.46,2826.51 3022.46,3947.01 ; 3281.66,2826.51 3281.66,3947.01 ; 3656.9,2826.51 3656.9,3947.01 ; 4381.45,2826.51 4381.45,3947.01 ; 1715.81,2826.51 4948,2826.51 4948,3947.01 1715.81,3947.01 1715.81,2826.51
  text "Symbol" at 1790.51,3859.86 h72
  text "Quantity" at 2091.17,3859.86 h72
  text "Finished Hole Size" at 2423.33,3859.86 h72
  text "Plated" at 3059.81,3859.86 h72
  text "Hole Type" at 3319.01,3859.86 h72
  text "Drill Layer Pair" at 3694.25,3859.86 h72
  text "Hole Tolerance" at 4418.8,3859.86 h72
  text "12" at 2091.17,3735.36 h60
  text "7.87mil (0.200mm)" at 2423.33,3735.36 h60
  text "PTH" at 3059.81,3735.36 h60
  text "Round" at 3319.01,3735.36 h60
  text "Top Layer - Bottom Layer" at 3694.25,3735.36 h60
  text "4" at 2091.17,3610.86 h60
  text "10.00mil (0.254mm)" at 2423.33,3610.86 h60
  text "PTH" at 3059.81,3610.86 h60
  text "Round" at 3319.01,3610.86 h60
  text "Top Layer - Bottom Layer" at 3694.25,3610.86 h60
  text "117" at 2091.17,3486.36 h60
  text "16.00mil (0.406mm)" at 2423.33,3486.36 h60
  text "PTH" at 3059.81,3486.36 h60
  text "Round" at 3319.01,3486.36 h60
  text "Top Layer - Bottom Layer" at 3694.25,3486.36 h60
  text "2" at 2091.17,3361.86 h60
  text "39.37mil (1.000mm)" at 2423.33,3361.86 h60
  text "PTH" at 3059.81,3361.86 h60
  text "Round" at 3319.01,3361.86 h60
  text "Top Layer - Bottom Layer" at 3694.25,3361.86 h60
  text "+3.94mil/-1.97mil" at 4418.8,3361.86 h60
  text "8" at 2091.17,3237.36 h60
  text "40.00mil (1.016mm)" at 2423.33,3237.36 h60
  text "PTH" at 3059.81,3237.36 h60
  text "Round" at 3319.01,3237.36 h60
  text "Top Layer - Bottom Layer" at 3694.25,3237.36 h60
  text "3" at 2091.17,3112.86 h60
  text "40.16mil (1.020mm)" at 2423.33,3112.86 h60
  text "PTH" at 3059.81,3112.86 h60
  text "Round" at 3319.01,3112.86 h60
  text "Top Layer - Bottom Layer" at 3694.25,3112.86 h60
  text "4" at 2091.17,2988.36 h60
  text "49.21mil (1.250mm)" at 2423.33,2988.36 h60
  text "PTH" at 3059.81,2988.36 h60
  text "Round" at 3319.01,2988.36 h60
  text "Top Layer - Bottom Layer" at 3694.25,2988.36 h60
  text "150 Total" at 2091.17,2863.86 h60
  text ".Layer_Name" at -244.43,-817.99 h60
M17 Embedded Cavity:
  text ".Layer_Name" at -244.43,-817.99 h60
M18 Embedded Assembly:
  text ".Layer_Name" at -244.43,-817.99 h60
M19 Embedded Keepout:
  text ".Layer_Name" at -240.49,-821.92 h60

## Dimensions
0,0 to 0,1624.02 on M2 Board Dimensions
0,0 to 2106.3,-0.01 on M2 Board Dimensions
-742.69,-359.49 to 257.31,-359.49 on M2 Board Dimensions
